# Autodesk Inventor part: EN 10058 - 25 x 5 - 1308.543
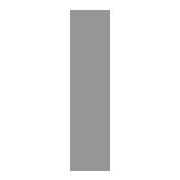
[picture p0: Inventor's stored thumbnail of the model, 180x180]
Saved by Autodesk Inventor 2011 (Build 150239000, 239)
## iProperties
_CCFamilyMember: 18
_CCFamilyDisplayName: DIN EN 10058 - Hot rolled flat steel bars for general purposes
_FrameMemberDoc: Frame Member File
_Version: 15.0.0
_GetPNFromCC: 1
Created: 2010-02
Part Number: EN 10058 - 25 x 5 - 1308.543
Material: Steel, Mild
Description: flat steel bar 25*5
Document SubType Name: Modeling
Standard: DIN
Designer: PC
Standard Revision: 2004
Standards Organization: DIN
Language: en-US
Size Designation: 25 x 5
Categories: <MemberInstance><Categories><Category DisplayName="Structural Shapes" InternalName="089c4875-fa83-4c05-b084-43b9cc11f5ed" Mnemonic="GRDR"><CategoryParameter Dis
Stock Number: 25 x 5
Density: 7.86 g/cm^3
Mass: 1285.64 g
Surface Area: 787.626 cm^2
Volume: 163.568 cm^3
IsCustomPart: 1
G_L: 1308.543 mm
G_W: 5.000 mm
G_H: 25.000 mm
Author: PC
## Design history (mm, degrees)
node "Start plane"
node "End plane"
sketch "Sketch"
  geometry: L1 (2.5, -12.5)-(-2.5, -12.5); L2 (-2.5, -12.5)-(-2.5, 12.5); L3 (-2.5, 12.5)-(2.5, 12.5); L4 (2.5, 12.5)-(2.5, -12.5); L5 (-6, 0)-(8, 0); L6 (0, -30)-(0, 40); L7 (0, 54)-(0, -44) reference; L8 (-9.2, 0)-(13.2, 0) reference
  constraints: 12 end point, 2 collinear, 2 parallel, 1 horizontal, 1 perpendicular
  dimensions: "d0" = 25 distance between parallel lines of L3 L1 (= G_W); "d1" = 5 distance between parallel lines of L4 L2 (= G_H); "d4" = 2.5 distance between parallel lines of L6 L4 (= 0.5 x d1); "d5" = 12.5 distance between parallel lines of L5 L3 (= 0.5 x d0)
extrude "Body" new body sketch "Sketch" stored distance "d2" = 1308.54288 (= G_L); taper "d3" = 0 deg
node "Driven Length"
  sketch "Sketch3"
    geometry: L1 (0, 0)-(10, 0) reference
    constraints: 2 end point, 1 horizontal
  workplane "Work Plane3"
  sketch "Sketch4"
    geometry: L1 (-2, 0)-(12, 0) reference; L2 (-2, 1308.543)-(12, 1308.543) reference
    dimensions: "d9" = 1308.54288 distance between parallel lines of L1 L2 (derived)
body "Solid1"
other parameters: "G_W" = 25 [user parameter; used in 1 equation term], "G_H" = 5 [user parameter; used in 1 equation term], "G_L" = 1308.54288 (= d9) [user parameter; used in 1 equation term], "G_OFFSET_START" = 0 [user parameter; used in 1 equation term], "G_OFFSET_END" = 0 [user parameter; used in 1 equation term], "d6" = 0 (computed from G_OFFSET_START), "d7" = 1308.54288 (= G_OFFSET_END + B_L), "B_L" = 1308.54288 [user parameter; used in 1 equation term], "d8" = 90 deg, "MAS" = 0.0981 [user parameter]
